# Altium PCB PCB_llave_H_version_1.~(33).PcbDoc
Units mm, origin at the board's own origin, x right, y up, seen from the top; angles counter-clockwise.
Board outline 232.16 x 155.45 mm, 2 copper layers (Top Layer, Bottom Layer); 60 components, 32 nets, 175 pads, 0 vias.
Unrouted connection lines stored in the file: 73.
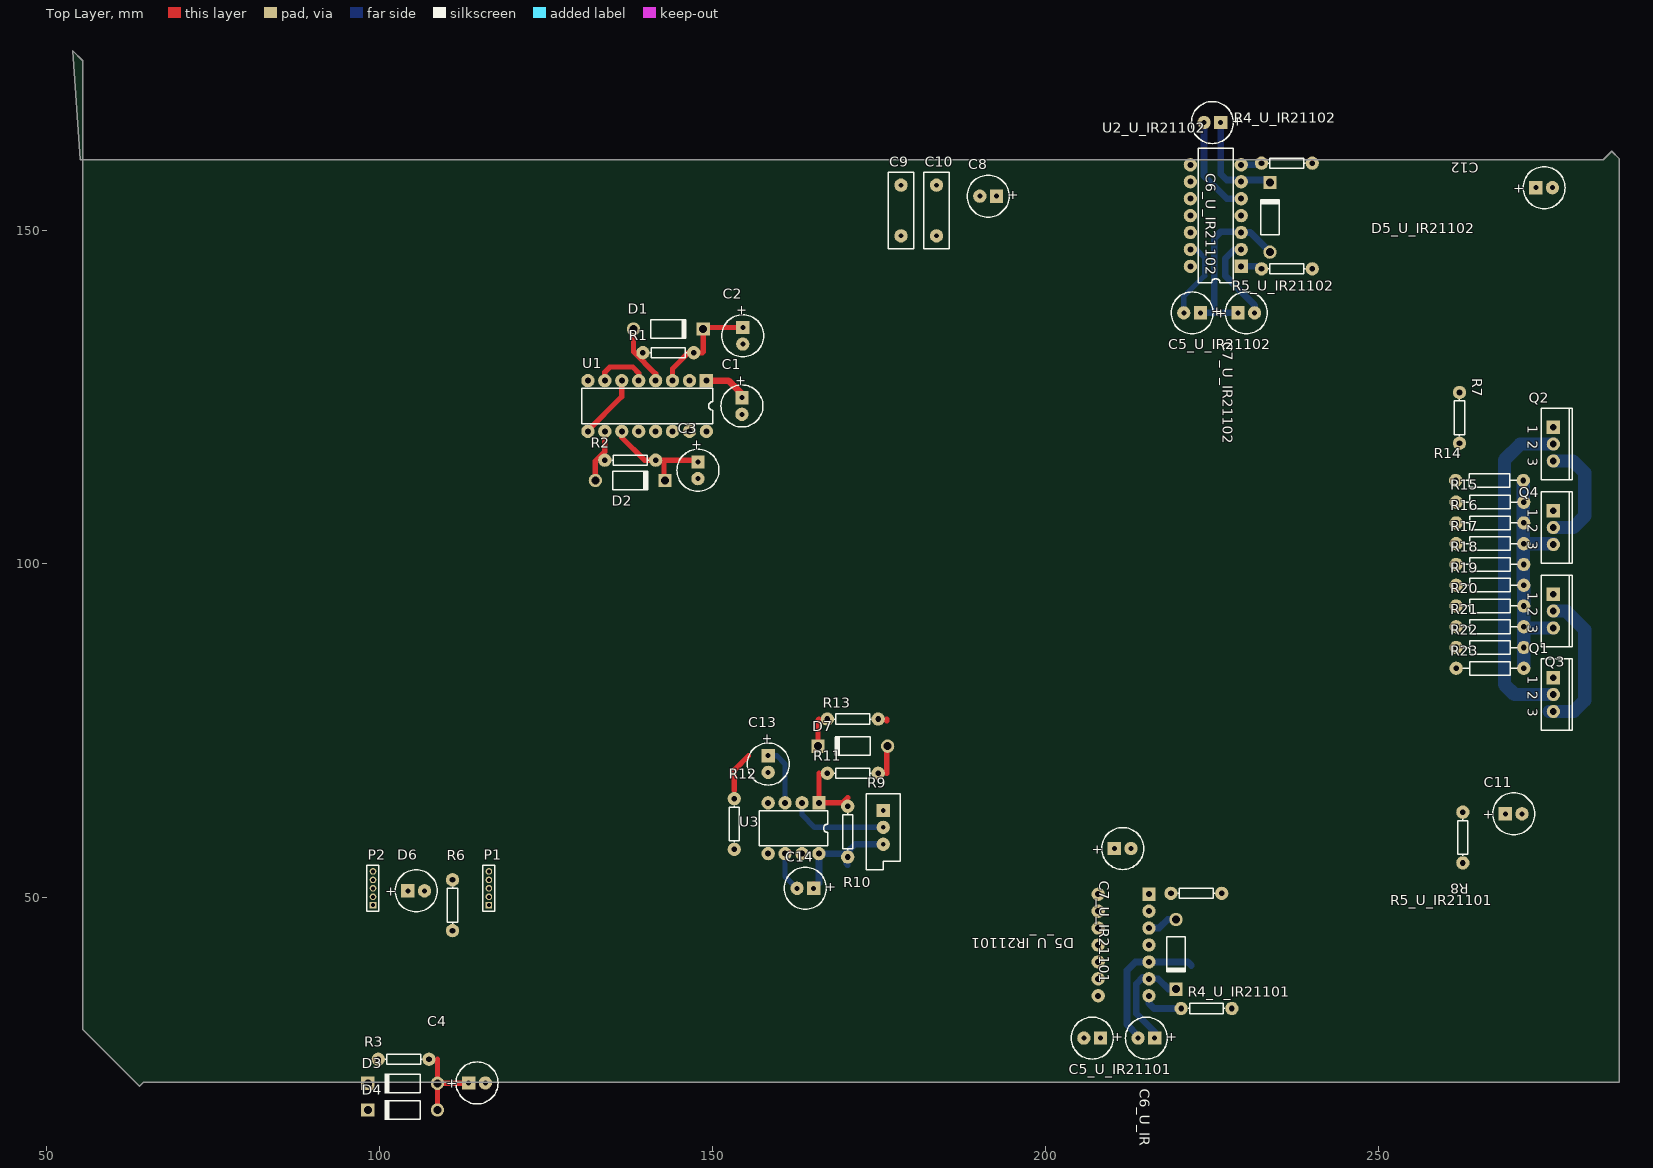
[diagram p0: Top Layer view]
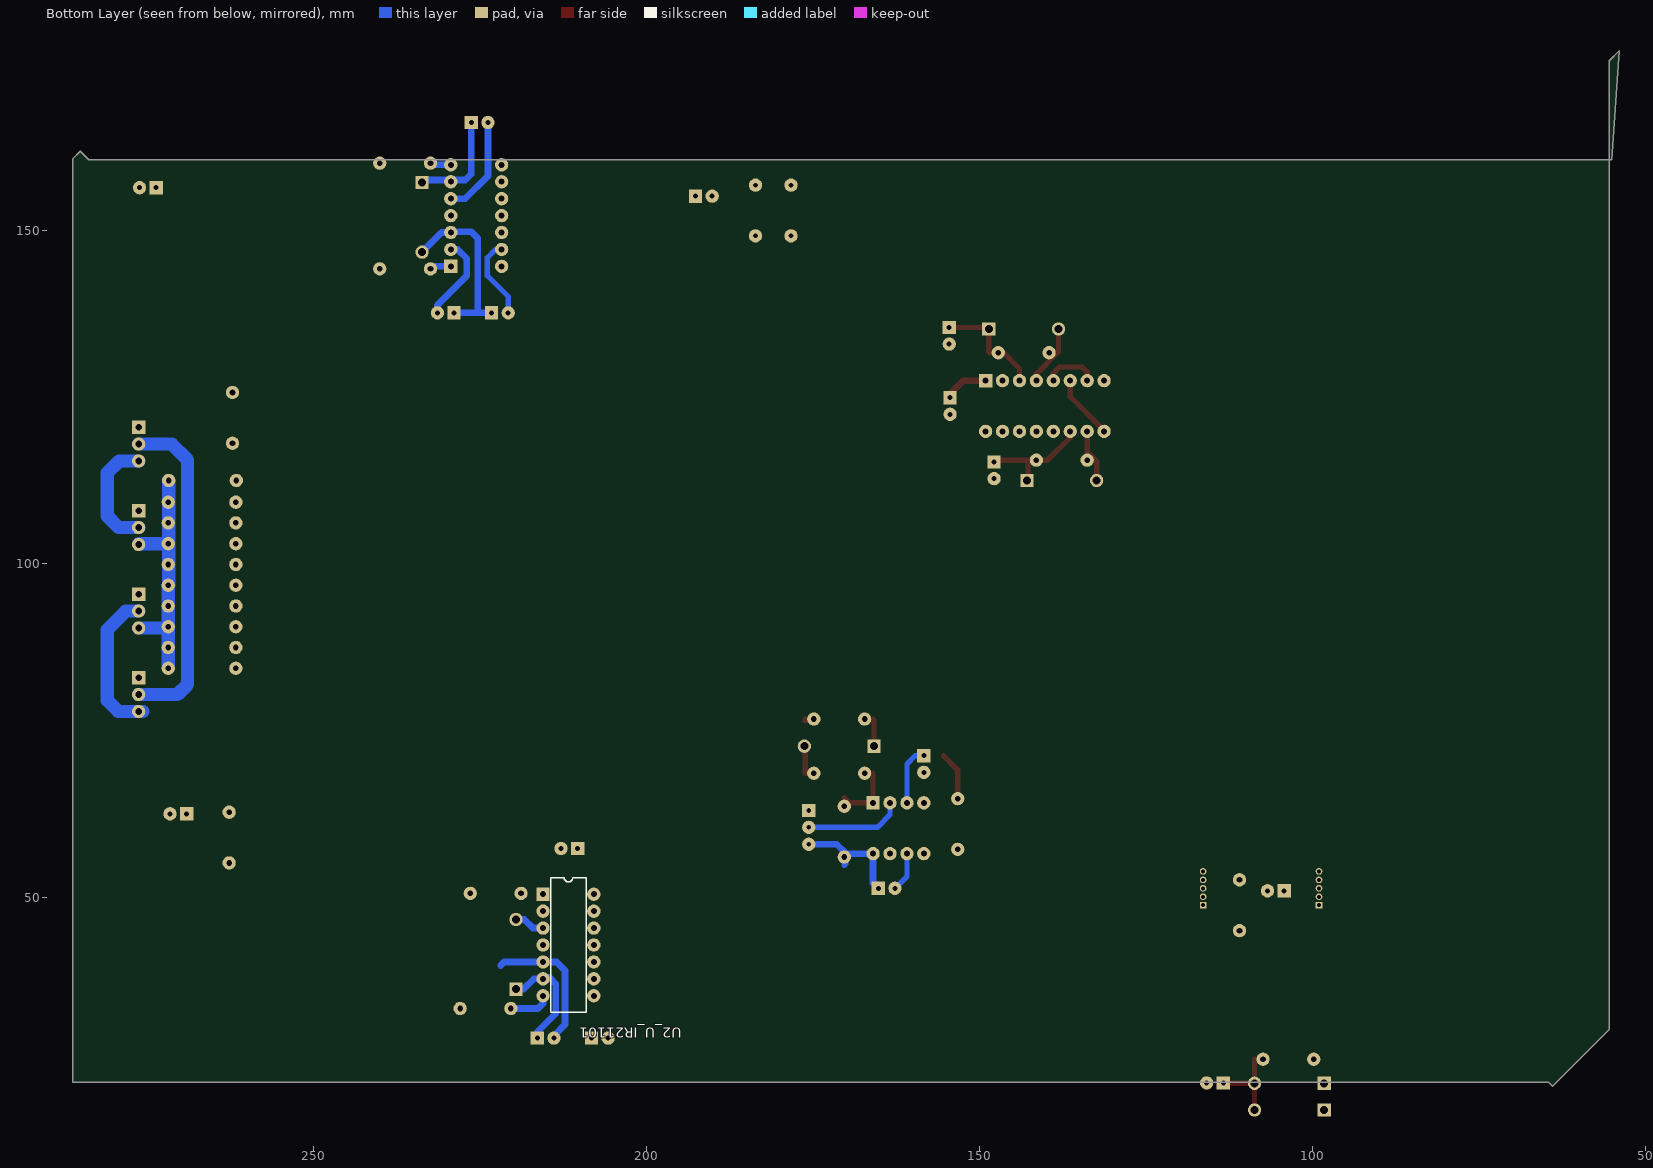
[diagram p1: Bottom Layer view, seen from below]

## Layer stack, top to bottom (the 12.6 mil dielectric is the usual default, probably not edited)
Top Layer: signal copper 0.0356
Dielectric: dielectric 0.32, FR-4, Dk 4.8
Bottom Layer: signal copper 0.0356

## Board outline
53.975,177.038 55.499,175.514 55.499,30.099 64.008,21.59 64.643,22.225 286.131,22.225 286.131,160.782 284.988,161.925 283.718,160.655 55.118,160.655

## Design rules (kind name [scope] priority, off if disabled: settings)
Clearance [All] p1: gap=0.4
ComponentClearance [All] p1: gap=0.254 collisioncheckmode=2 verticalgap=0.254
PolygonConnect [All] p1: connectstyle=Relief reliefconductorwidth=0.254 reliefentries=4 polygonreliefangle="90 Angle"
RoomDefinition U_IR21102 [InComponentClass('U_IR21102')] p1: confinementstyle=ConfineIn formatcopy=TRUE lockcomponents=FALSE outline 218.44,170.18 245.237,170.18 245.237,134.239 218.44,134.239
RoomDefinition U_Puente_H [InComponentClass('U_Puente_H')] p2: confinementstyle=ConfineOut formatcopy=TRUE lockcomponents=FALSE outline 302.133,128.016 302.133,110.363 311.531,110.363 311.531,128.016
RoomDefinition U_INITShutdown [InComponentClass('U_INITShutdown')] p3: confinementstyle=ConfineIn formatcopy=TRUE lockcomponents=FALSE outline 90.297,32.893 141.097,32.893 141.097,13.97 90.297,13.97
RoomDefinition U_Shutdown [InComponentClass('U_Shutdown')] p4: confinementstyle=ConfineIn formatcopy=TRUE lockcomponents=FALSE outline 142.113,82.931 192.913,82.931 192.913,22.225 142.113,22.225
RoomDefinition Llave_H_esquema [InComponentClass('Llave_H_esquema')] p5: confinementstyle=ConfineIn formatcopy=TRUE lockcomponents=FALSE outline 97.917,40.513 118.237,40.513 118.237,57.531 97.917,57.531
RoomDefinition U_4049 [InComponentClass('U_4049')] p6: confinementstyle=ConfineIn formatcopy=TRUE lockcomponents=FALSE outline 120.904,108.712 162.56,108.712 162.56,141.478 120.904,141.478
RoomDefinition U_IR21101 [InComponentClass('U_IR21101')] p7: confinementstyle=ConfineIn formatcopy=TRUE lockcomponents=FALSE outline 199.136,61.341 231.394,61.341 231.394,20.32 199.136,20.32
RoutingVias [All] p1: holewidth=0.711 width=1.27 viastyle="Through Hole" minholewidth=0.711 minwidth=1.27 maxholewidth=0.711 maxwidth=1.27
SolderMaskExpansion [All] p1: expansion=0.102
TestPointUsage [All] p1: valid=0 allowmultiple=FALSE
Testpoint [All] p1: side=15 testpointundercomponent=TRUE minsize=1.016 maxsize=2.54 preferedsize=1.524 minholesize=0 maxholesize=1.016 preferedholesize=0.813 testpointgrid=0.025 style=1023 order=0-112345678
Width [All] p1: maxlimit=3 minlimit=0.8 preferedwidth=1
18 further rules are at their usual default settings.

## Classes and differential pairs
component class U_INITShutdown: C4 D3 D4 R3
channel class IR2110: U_IR21101 U_IR21102
component class U_Shutdown: C13 C14 D7 R9 R10 R11 R12 R13 R14 R15 R16 R17 R18 R19 R20 R21 R22 R23 U3
component class U_Puente_H: C8 C9 C10 C11 C12 Q1 Q2 Q3 Q4 R7 R8
component class U_IR21102: C5_U_IR21102 C6_U_IR21102 C7_U_IR21102 D5_U_IR21102 R4_U_IR21102 R5_U_IR21102 U2_U_IR21102
component class U_IR21101: C5_U_IR21101 C6_U_IR21101 C7_U_IR21101 D5_U_IR21101 R4_U_IR21101 R5_U_IR21101 U2_U_IR21101
component class U_4049: C1 C2 C3 D1 D2 R1 R2 U1
component class Llave_H_esquema: D6 P1 P2 R6

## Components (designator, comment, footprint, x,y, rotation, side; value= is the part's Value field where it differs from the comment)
C1 "Cap Pol1" CAPPR2.5-6.3X5 154.432,123.698 r270 top
C2 "Cap Pol1" CAPPR2.5-6.3X5 154.559,134.239 r270 top
C3 "Cap Pol1" CAPPR2.5-6.3X5 147.828,114.046 r270 top
C4 "Cap Pol1" CAPPR2.5-6.3X5 114.681,22.098 r0 top
C5_U_IR21101 "Cap Pol1" CAPPR2.5-6.3X5 207.01,28.829 r180 top (schematic designator C5)
C5_U_IR21102 "Cap Pol1" CAPPR2.5-6.3X5 221.996,137.668 r180 top (schematic designator C5)
C6_U_IR21101 "Cap Pol1" CAPPR2.5-6.3X5 215.138,28.829 r180 top (schematic designator C6)
C6_U_IR21102 "Cap Pol1" CAPPR2.5-6.3X5 225.044,166.243 r180 top (schematic designator C6)
C7_U_IR21101 "Cap Pol1" CAPPR2.5-6.3X5 211.582,57.277 r0 top (schematic designator C7)
C7_U_IR21102 "Cap Pol1" CAPPR2.5-6.3X5 230.124,137.668 r0 top (schematic designator C7)
C8 "Cap Pol1" CAPPR2.5-6.3X5 191.389,155.194 r180 top
C9 "Cap" RAD-0.3 178.308,153.035 r90 top
C10 "Cap" RAD-0.3 183.642,153.035 r90 top
C11 "Cap Pol1" CAPPR2.5-6.3X5 270.256,62.484 r0 top
C12 "Cap Pol1" CAPPR2.5-6.3X5 274.828,156.464 r0 top
C13 "Cap Pol1" CAPPR2.5-6.3X5 158.369,69.957 r270 top
C14 "Cap Pol1" CAPPR2.5-6.3X5 163.957,51.308 r180 top
D1 "Diode" DO-204AL 143.383,135.255 r0 top
D2 "Diode" DO-204AL 137.668,112.522 r0 top
D3 "Diode" DO-204AL 103.505,22.036 r180 top
D4 "Diode" DO-204AL 103.505,18.034 r180 top
D5_U_IR21101 "Diode" DO-204AL 219.583,41.402 r270 top (schematic designator D5)
D5_U_IR21102 "Diode" DO-204AL 233.68,152.019 r90 top (schematic designator D5)
D6 "LED0" CAPPR2.5-6.3X5 105.537,50.927 r0 top
D7 "Diode" DO-204AL 171.069,72.644 r180 top
P1 "MHDR1X5" MHDR1X5 116.459,48.768 r90 top
P2 "MHDR1X5" MHDR1X5 99.06,48.768 r90 top
Q1 "IRF3205" TO-220AB 276.225,80.391 r270 top
Q2 "IRF3205" TO-220AB 276.225,117.983 r270 top
Q3 "IRF3205" TO-220AB 276.225,92.922 r270 top
Q4 "IRF3205" TO-220AB 276.225,105.452 r270 top
R1 "Res2" AXIAL-0.3 143.383,131.699 r180 top
R2 "Res2" AXIAL-0.3 137.668,115.57 r0 top
R3 "Res2" AXIAL-0.3 103.661,25.654 r180 top
R4_U_IR21101 "Res2" AXIAL-0.3 224.155,33.274 r0 top (schematic designator R4)
R4_U_IR21102 "Res2" AXIAL-0.3 236.22,160.147 r0 top (schematic designator R4)
R5_U_IR21101 "Res2" AXIAL-0.3 222.631,50.546 r0 top (schematic designator R5)
R5_U_IR21102 "Res2" AXIAL-0.3 236.22,144.272 r0 top (schematic designator R5)
R6 "Res2" AXIAL-0.3 110.998,48.768 r90 top
R7 "Res2" AXIAL-0.3 262.128,121.92 r270 top
R8 "Res2" AXIAL-0.3 262.636,58.928 r90 top
R9 "RPot" VR5 175.641,60.452 r270 top
R10 "Res2" AXIAL-0.3 170.307,59.817 r270 top
R11 "Res2" AXIAL-0.3 171.069,68.58 r0 top
R12 "Res2" AXIAL-0.3 153.289,60.96 r90 top
R13 "Res2" AXIAL-0.3 171.069,76.708 r180 top
R14 "Res2" AXIAL-0.4 266.633,112.522 r0 top
R15 "Res2" AXIAL-0.4 266.7,109.266 r0 top
R16 "Res2" AXIAL-0.4 266.7,106.149 r0 top
R17 "Res2" AXIAL-0.4 266.7,103.031 r0 top
R18 "Res2" AXIAL-0.4 266.7,99.914 r0 top
R19 "Res2" AXIAL-0.4 266.7,96.797 r0 top
R20 "Res2" AXIAL-0.4 266.7,93.68 r0 top
R21 "Res2" AXIAL-0.4 266.7,90.562 r0 top
R22 "Res2" AXIAL-0.4 266.7,87.445 r0 top
R23 "Res2" AXIAL-0.4 266.7,84.328 r0 top
U1 "MC54HC4049J" 620-09 140.208,123.698 r180 top
U2_U_IR21101 "IR2110" PDIP14 211.709,42.799 r270 bottom (schematic designator U2)
U2_U_IR21102 "IR2110" PDIP14 225.552,152.273 r90 top (schematic designator U2)
U3 "LM393N" 626-05 162.179,60.325 r180 top

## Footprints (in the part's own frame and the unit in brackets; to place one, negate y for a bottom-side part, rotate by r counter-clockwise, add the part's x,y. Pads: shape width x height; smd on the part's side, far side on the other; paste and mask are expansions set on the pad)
620-09 [mm] "DIP; 16 Leads; Row Spacing 7.62 mm; Pitch 2.54 mm"
  rect 2x2 hole 0.9: 1(-8.89,-3.81)
  round 2 hole 0.9: 2(-6.35,-3.81) 3(-3.81,-3.81) 4(-1.27,-3.81) 5(1.27,-3.81) 6(3.81,-3.81) 7(6.35,-3.81) 8(8.89,-3.81) 9(8.89,3.81) 10(6.35,3.81) 11(3.81,3.81) 12(1.27,3.81) 13(-1.27,3.81) 14(-3.81,3.81) 15(-6.35,3.81) 16(-8.89,3.81)
  silkscreen extent -9.85,-2.65 9.85,2.65
626-05 [mm] "DIP; 8 Leads; Row Spacing 7.62 mm; Pitch 2.54 mm"
  rect 2x2 hole 0.9: 1(-3.81,-3.81)
  round 2 hole 0.9: 2(-1.27,-3.81) 3(1.27,-3.81) 4(3.81,-3.81) 5(3.81,3.81) 6(1.27,3.81) 7(-1.27,3.81) 8(-3.81,3.81)
  silkscreen extent -5.15,-2.65 5.15,2.65
AXIAL-0.3 [mm] "Resistor; 2 Leads"
  round 2 hole 0.85: 1(-3.81,0) 2(3.81,0)
  silkscreen extent -2.77,-0.76 2.77,0.76
AXIAL-0.4 [mm] "Resistor; 2 Leads"
  round 2 hole 0.85: 1(-5.08,0) 2(5.08,0)
  silkscreen extent -4.06,-1.02 4.06,1.02
CAPPR2.5-6.3X5 [mm] "Capacitor, Electrolytic, Radial; Body 6.3 x 5 mm (Dia.xH typ); Pin Spacing 2.5 mm (typ)"
  rect 2x2 hole 0.75: 1(-1.25,0)
  round 2 hole 0.75: 2(1.25,0)
  silkscreen extent -3.15,-3.15 3.15,3.15
DO-204AL [mm] "Diode, Axial; Body 5.2 x 2.7 mm (LxDia. max), Lead Dia. 0.86 mm (max)"
  round 2 hole 1.2: 1(-5.23,0)
  rect 2x2 hole 1.2: 2(5.23,0)
  silkscreen extent -2.65,-1.4 2.75,1.4
MHDR1X5 [mm] "Connector; Header; 5 Position"
  rect 1x1 hole 0.6: 1(0,0)
  round 1 hole 0.6: 2(1.27,0) 3(2.54,0) 4(3.81,0) 5(5.08,0)
  silkscreen extent -0.9,-0.9 5.98,0.9
PDIP14 [mm] "DIP; 14 Leads; Row Spacing 7.62 mm; Pitch 2.54 mm"
  rect 2x2 hole 0.9: 1(-7.62,-3.81)
  round 2 hole 0.9: 2(-5.08,-3.81) 3(-2.54,-3.81) 4(0,-3.81) 5(2.54,-3.81) 6(5.08,-3.81) 7(7.62,-3.81) 8(7.62,3.81) 9(5.08,3.81) 10(2.54,3.81) 11(0,3.81) 12(-2.54,3.81) 13(-5.08,3.81) 14(-7.62,3.81)
  silkscreen extent -10.1,-2.65 10.1,2.65
RAD-0.3 [mm] "Capacitor; 2 Leads"
  round 2 hole 0.7: 1(-3.81,0) 2(3.81,0)
  silkscreen extent -5.71,-1.91 5.71,1.91
TO-220AB [mm] "TO, Thru-Hole, Vertical, Heatsink Mounted; 3 In-Line Leads; Pitch 2.54 mm"
  rect 2x2 hole 1: 1(-2.54,0)
  round 2 hole 1: 2(0,0) 3(2.54,0)
  silkscreen extent -5.35,-1.85 5.35,2.85
VR5 [mm] "Potentiometer; 3 Leads"
  rect 2x2 hole 0.7: 1(-2.54,0)
  round 2 hole 0.7: 2(2.54,0) 3(0,0)
  silkscreen extent -5.08,-2.54 6.35,2.54

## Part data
C1 C2 C3 C4 C5_U_IR21101 C5_U_IR21102 C6_U_IR21101 C6_U_IR21102 C7_U_IR21101 C7_U_IR21102 C8 C11 C12 C13 C14: "Polarized Capacitor (Radial)"
C9 C10: "Capacitor"
D1 D2 D3 D4 D5_U_IR21101 D5_U_IR21102 D7: "Default Diode"
D6: "Typical INFRARED GaAs LED"
P1 P2: "Header, 5-Pin"
Q1 Q2 Q3 Q4: "HEXFET Power MOSFET"
R1 R2 R3 R4_U_IR21101 R4_U_IR21102 R5_U_IR21101 R5_U_IR21102 R6 R7 R8 R10 R11 R12 R13 R14 R15 R16 R17 R18 R19 R20 R21 R22 R23: "Resistor"
R9: "Potentiometer"
U1: "Hex Inverting Buffer/Logic-Level Down Converter"
U2_U_IR21101 U2_U_IR21102: "High and Low Side Driver"
U3: "Dual Comparator"

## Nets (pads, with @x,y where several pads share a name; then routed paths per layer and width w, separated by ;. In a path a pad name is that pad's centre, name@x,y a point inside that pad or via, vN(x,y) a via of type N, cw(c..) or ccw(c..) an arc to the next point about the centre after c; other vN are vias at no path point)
COM_U_IR21101: C7_U_IR21101.2 C7_U_IR21102.2 C11.2 C12.2 Q3.3 Q4.3 R7.1 R8.1 R12.1 R14.2 R15.2 R16.2 R17.2 R18.2 R19.2 R20.2 R21.2 R22.2 R23.2 U2_U_IR21101.2 U2_U_IR21102.2 | length 54.3
  Bottom Layer w1: U2_U_IR21102.2 228.346,147.193 226.949,145.796 226.949,143.256 231.374,138.831 C7_U_IR21102.2 ; R17.2@271.713,102.997 271.798,102.912 Q4.3
  Bottom Layer w2: R19.2@271.713,96.774 271.78,96.707 R23.2@271.78,84.582 ; R19.2@271.713,96.797 271.713,102.965 R17.2 Q4.3@276.191,103.031 ; R17.2@271.713,102.997 R14.2 ; R21.2@271.822,90.382 Q3.3
GND: C1.2 C2.2 C3.2 C4.2 C5_U_IR21101.2 C5_U_IR21102.2 C8.2 C9.1 C10.1 C13.2 C14.2 D6.2 P1.1 P2.4 R9.1 R13.1 R14.1 R15.1 R16.1 R17.1 R18.1 R19.1 R20.1 R21.1 R22.1 R23.1 U1.8 U2_U_IR21101.13 U2_U_IR21102.13 U3.4 U3.5 U3.6 | length 18.5
  Top Layer w0.8: U3.5 158.389,56.535 U3.5@158.369,56.555 ; U3.6@160.889,56.535 U3.6 ; 176.149,76.454 176.149,76.708
  Bottom Layer w0.8: U3.6 160.909,53.106 C14.2 ; C5_U_IR21102.2 220.746,140.101 223.901,143.256 223.901,145.923 222.631,147.193 U2_U_IR21102.13
HIN_U_IR21101: U1.12 U2_U_IR21101.10 U2_U_IR21102.12
HIN_U_IR21102: U1.2 U2_U_IR21101.12 U2_U_IR21102.10
HO1: Q2.1 R4_U_IR21102.2
HO2: Q1.1 R4_U_IR21101.2
IN_SD: D4.2 P2.3
LO1: Q4.1 R5_U_IR21102.2 R7.2
LO2: Q3.1 R5_U_IR21101.2 R8.2
MOTOR+: C6_U_IR21102.2 Q2.3 Q4.2 U2_U_IR21102.5 | length 32.3
  Bottom Layer w1: C6_U_IR21102.2 223.794,158.222 227.203,154.813 U2_U_IR21102.5
  Bottom Layer w2: Q4.2 279.188,105.452 280.924,107.188 280.924,113.665 279.146,115.443 Q2.3
MOTOR-: C6_U_IR21101.2 Q1.3 Q3.2 U2_U_IR21101.5 | length 43.8
  Bottom Layer w1: C6_U_IR21101.2 213.888,29.19 212.217,30.861 212.217,38.989 213.487,40.259 221.361,40.259 221.889,39.731
  Bottom Layer w2: Q1.3@275.59,77.851 279.273,77.851 280.924,79.502 280.924,90.128 278.13,92.922 Q3.2
NetC2_1: C2.1 D1.2 R1.1 U1.3 | length 16.9
  Top Layer w0.8: U1.3 144.018,129.286 146.431,131.699 148.463,131.699 148.613,131.849 D1.2 148.847,135.489 C2.1
NetC3_1: C3.1 D2.2 R2.2 U1.11 | length 17
  Top Layer w0.8: U1.11 136.398,118.999 139.827,115.57 147.554,115.57 C3.1 ; 142.748,115.57 142.748,112.672 D2.2
NetC4_1: C4.1 D3.1 D4.1 R3.1 | length 12.8
  Top Layer w0.8: D3.1@108.429,22.342 D3.1 113.369,22.036 C4.1 ; D4.1 108.741,18.04 108.741,25.654
NetC6_U_IR21101_1: C6_U_IR21101.1 D5_U_IR21101.2 U2_U_IR21101.6 | length 16.2
  Bottom Layer w1: U2_U_IR21101.6@215.392,37.973 214.63,37.973 213.617,36.96 213.617,32.509 216.388,29.738 C6_U_IR21101.1 ; U2_U_IR21101.6 216.916,37.719 218.463,36.172 D5_U_IR21101.2
NetC6_U_IR21102_1: C6_U_IR21102.1 D5_U_IR21102.2 U2_U_IR21102.6 | length 15.6
  Bottom Layer w1: C6_U_IR21102.1 226.294,158.516 227.203,157.607 233.322,157.607 D5_U_IR21102.2
NetC13_1: C13.1 R12.2 U3.3 | length 15.1
  Top Layer w0.8: 153.289,66.04 153.289,69.088 155.408,71.207 ; C13.1 C13.1@158.456,71.12
  Bottom Layer w0.8: C13.1 159.679,71.207 160.909,69.977 U3.3
NetD1_1: D1.1 R1.2 U1.4 | length 9.1
  Top Layer w0.8: D1.1 138.153,131.849 141.478,128.524 U1.4
NetD2_1: D2.1 R2.1 U1.10 | length 8
  Top Layer w0.8: D2.1 132.438,115.42 133.858,116.84 U1.10
NetD6_1: D6.1 R6.1
NetD7_1: D7.1 R11.2 | length 4.2
  Top Layer w0.8: 176.149,68.58 D7.1@176.149,72.771
NetR4_U_IR21101_1: R4_U_IR21101.1 U2_U_IR21101.7 | length 6.3
  Bottom Layer w1: U2_U_IR21101.7 215.519,34.036 216.281,33.274 R4_U_IR21101.1
NetR4_U_IR21102_1: R4_U_IR21102.1 U2_U_IR21102.7 | length 2.8
  Bottom Layer w1: U2_U_IR21102.7 R4_U_IR21102.1@232.156,159.893
NetR5_U_IR21101_1: R5_U_IR21101.1 U2_U_IR21101.1
NetR5_U_IR21102_1: R5_U_IR21102.1 U2_U_IR21102.1 | length 3.2
  Bottom Layer w1: U2_U_IR21102.1 232.029,144.653 R5_U_IR21102.1
NetR9_3: R9.3 U3.2 | length 14.8
  Bottom Layer w0.8: U3.2 163.449,62.357 165.354,60.452 R9.3
NetR10_1: R10.1 R11.1 U3.1 | length 9.1
  Top Layer w0.8: 165.989,68.58 U3.1 169.545,64.135 170.307,64.897
NetU1_6: U1.6 U1.9 | length 9.7
  Top Layer w0.8: U1.9 131.318,120.015 136.398,125.095 U1.6
PWM: P2.2 U1.5 U1.7 | length 8.2
  Top Layer w0.8: U1.7 133.858,128.778 134.62,129.54 138.049,129.54 138.938,128.651 U1.5
SD: D3.2 D7.2 R13.2 U2_U_IR21101.11 U2_U_IR21102.11 | length 4.1
  Top Layer w0.8: D7.2 165.839,76.558 165.989,76.708
VCC_MOTOR: C8.1 C9.2 C10.2 C11.1 C12.1 P1.2 Q1.2 Q2.2 | length 50
  Bottom Layer w2: Q1.2 270.383,80.391 268.879,81.895 268.879,115.59 271.272,117.983 Q2.2
VDD: C1.1 C5_U_IR21101.1 C5_U_IR21102.1 C7_U_IR21101.1 C7_U_IR21102.1 C14.1 D5_U_IR21101.1 D5_U_IR21102.1 P2.5 R3.2 R6.2 R9.2 R10.2 U1.1 U2_U_IR21101.3 U2_U_IR21101.9 U2_U_IR21102.3 U2_U_IR21102.9 U3.8 | length 58.6
  Top Layer w0.8: C1.1 C1.1@154.432,125.349 ; C14.1 C14.1@165.207,51.923 ; U3.8@165.862,56.769 165.989,56.642 U3.8
  Top Layer w1: U1.1 152.4,127.508 154.432,125.476 C1.1
  Bottom Layer w0.8: R10.2@170.053,56.515 170.053,54.991 170.307,54.737 170.307,56.734 R10.2@170.289,56.751
  Bottom Layer w1: C14.1 165.989,52.09 U3.8 R10.2@170.053,56.515 ; R10.2@170.289,56.751 171.45,57.912 R9.2 ; U2_U_IR21101.3 217.043,45.339 218.336,46.632 D5_U_IR21101.1 ; C5_U_IR21102.1 C7_U_IR21102.1 ; 225.425,137.668 225.298,137.795 225.298,148.844 226.314,149.86 U2_U_IR21102.3@229.108,149.86 ; U2_U_IR21102.3 230.736,149.733 D5_U_IR21102.1
pads on no net: P1.3 P1.4 P1.5 P2.1 U1.13 U1.14 U1.15 U1.16 U2_U_IR21101.4 U2_U_IR21101.8 U2_U_IR21101.14 U2_U_IR21102.4 U2_U_IR21102.8 U2_U_IR21102.14 U3.7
